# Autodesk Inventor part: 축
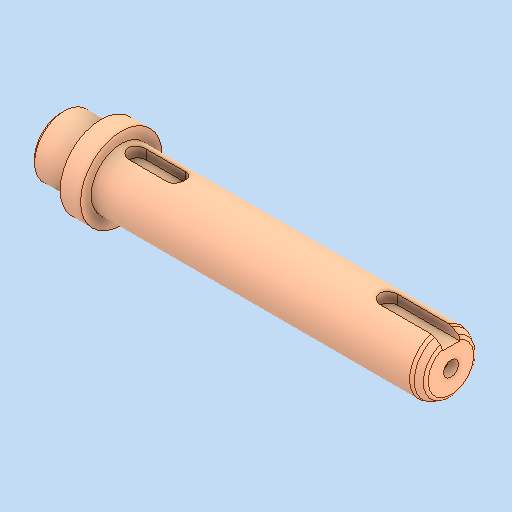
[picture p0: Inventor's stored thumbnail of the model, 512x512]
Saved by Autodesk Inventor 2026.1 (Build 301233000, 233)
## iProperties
Created: 2026-01
Part Number: 축
Material: 강철, 탄소
Document SubType Name: Modeling
Designer: PC-30
Density: 7.85 g/cm^3
Appearance: 기본값
Author: jhkim
Sending System: Autodesk Inventor 2026
Preprocessor: ST-DEVELOPER v20.1
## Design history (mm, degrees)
feature "솔리드1"
node "솔리드2"
